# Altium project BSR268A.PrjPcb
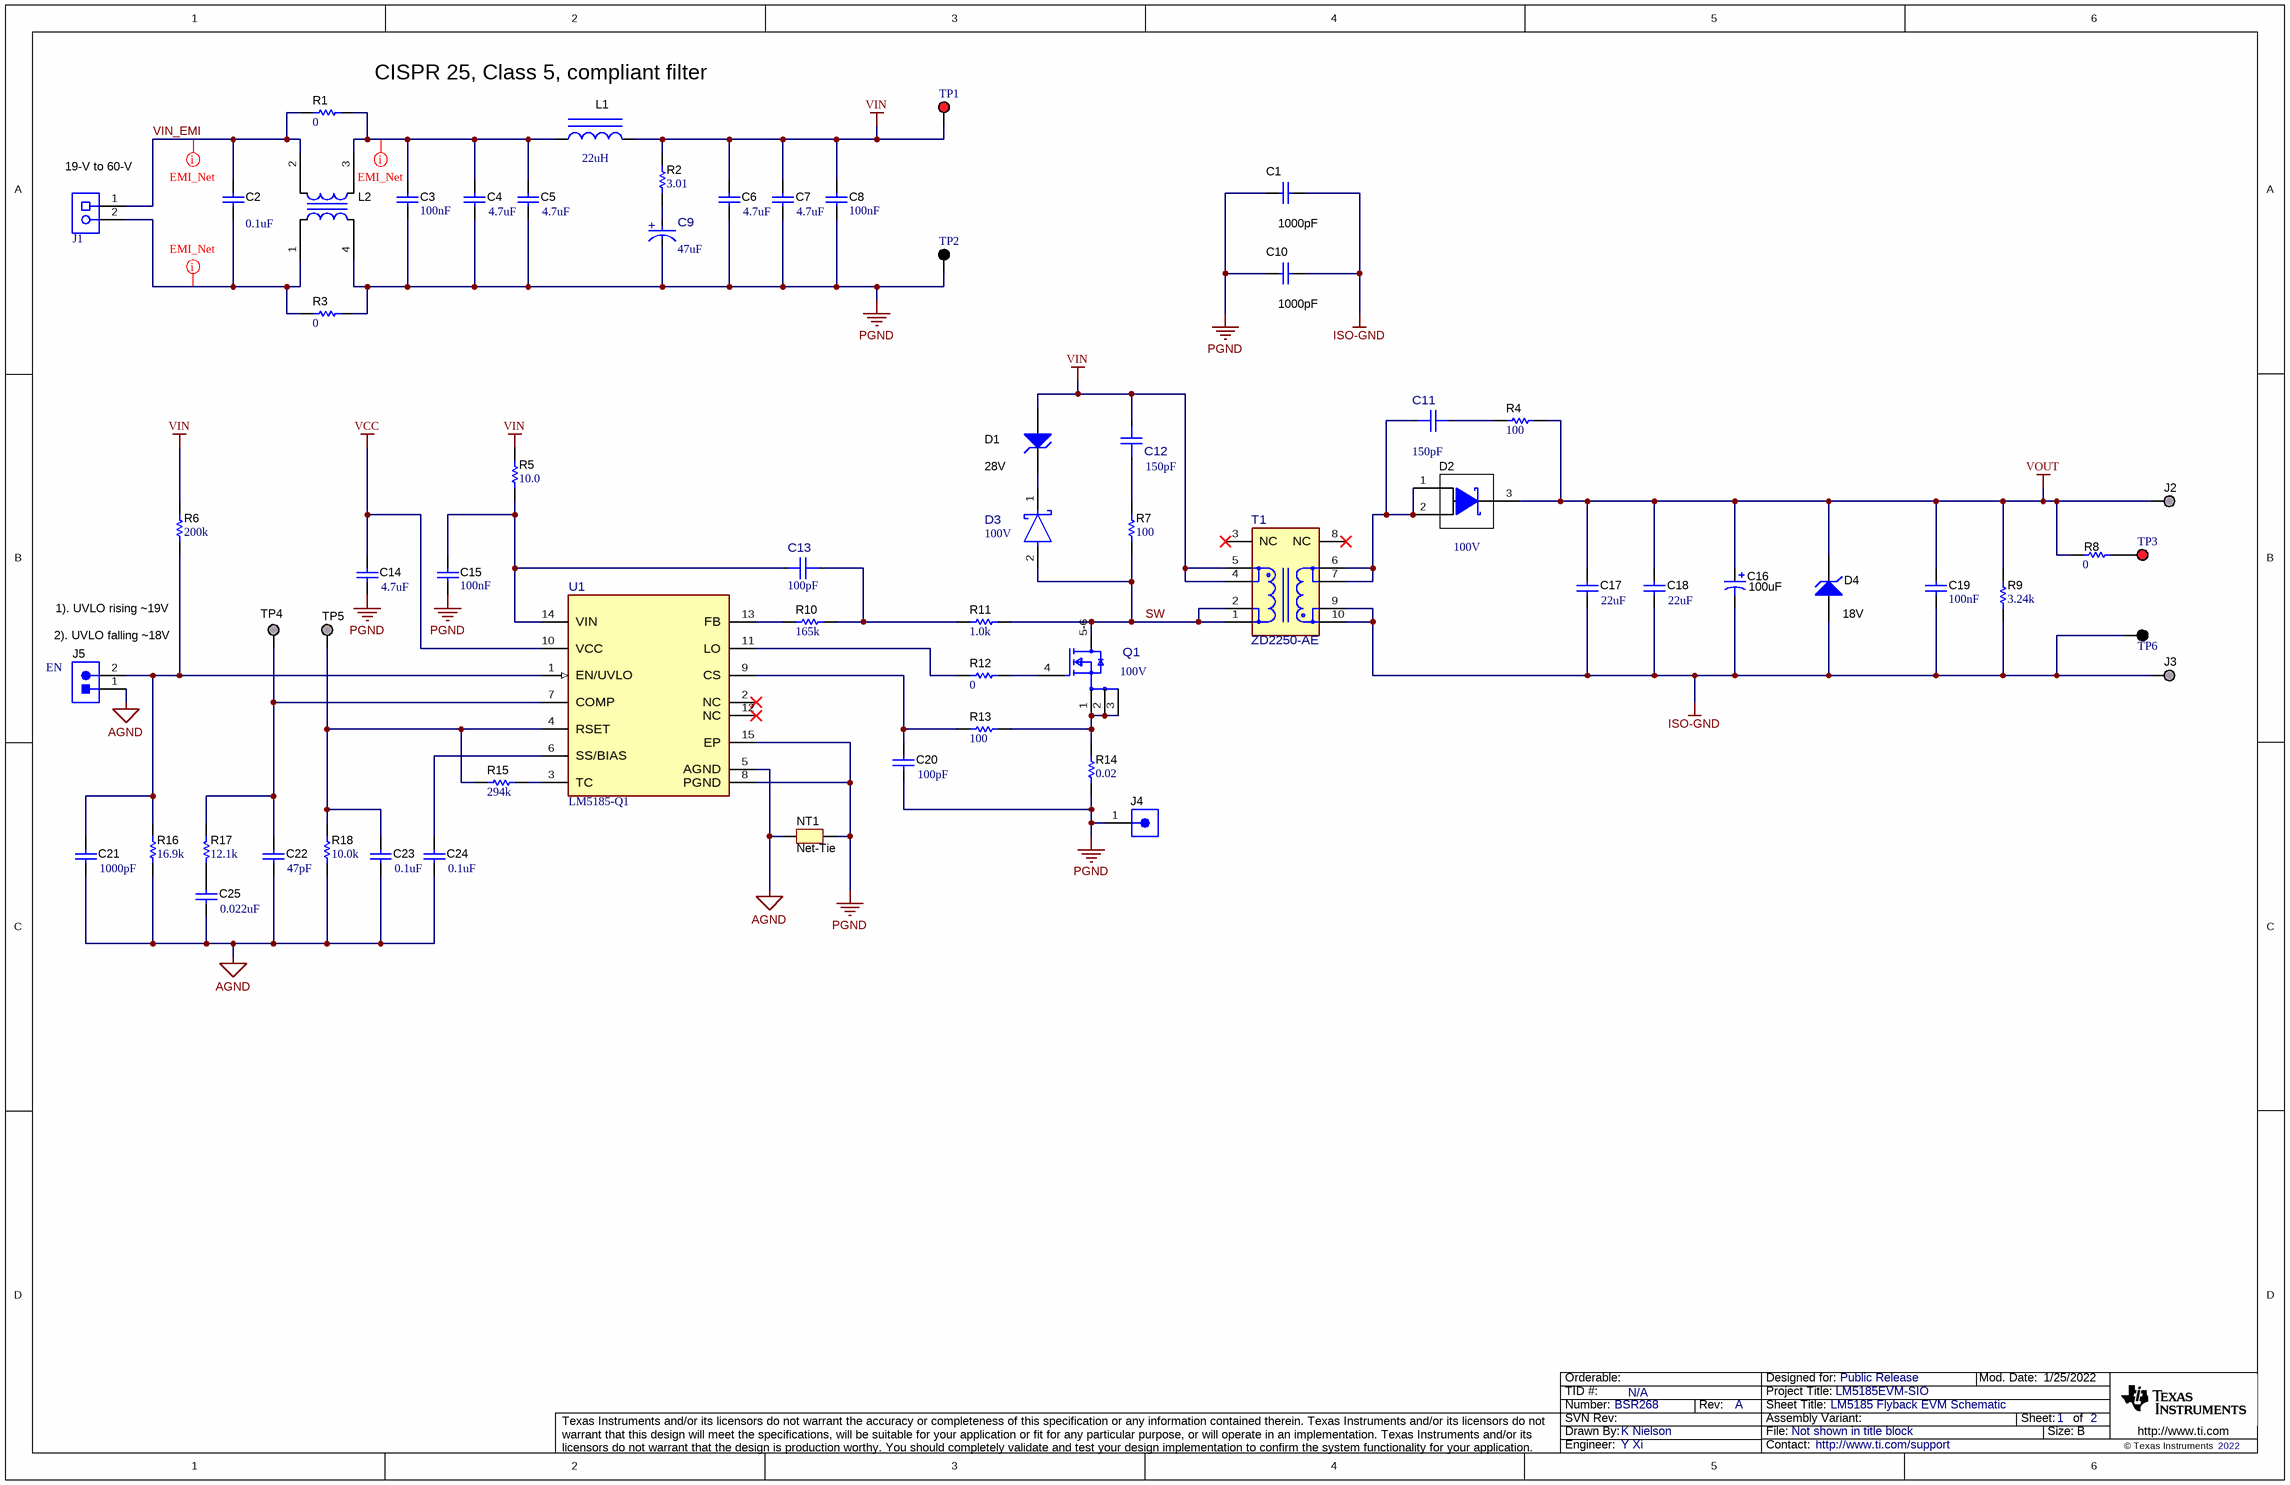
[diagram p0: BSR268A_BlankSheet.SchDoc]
CopyrightYear: 2022; PCB_Layout: K Nielson; PCB_Rev: A; PRJ_Customer: Public Release; PRJ_Engineer: Y Xi; PRJ_Number: BSR268; PRJ_Title: LM5185EVM-SIO; SCH_Rev: A; TechSupport: http://www.ti.com/support; TID: N/A
2 sheets, 91 parts. Net scope: global (net labels, ports and power ports of the same name join across sheets).
Board file: BSR268A.PcbDoc
Sheets:
  BSR268A_BlankSheet.SchDoc
  BSR268A_Hardware.SchDoc

## Sheet BSR268A_BlankSheet.SchDoc: LM5185 Flyback EVM Schematic
size 431 x 279 mm; Date: Not shown in title block; ApprovedBy: Not shown in title block; CheckedBy: Not shown in title block; Author: Not shown in title block; CompanyName: Not shown in title block; DrawnBy: K Nielson; Engineer: Not shown in title block; Organization: Not shown in title block; Address1: Not shown in title block; Address2: Not shown in title block; Address3: Not shown in title block; Address4: Not shown in title block; DocumentNumber: 2; Revision: Use project parameter SCH_Rev; SheetNumber: 1; SheetTotal: 2; PageSetup: Record=PageOptions¦CenterHorizontal=True¦CenterVertical=True¦PrintScale=1.00¦XCorrection=1.00¦YCorrection=1.00¦PrintKind=0¦BorderSize=5000000¦LeftOffset=0¦BottomOffset=0¦Orientation=2¦PaperLength=1000¦PaperWidth=1000¦Scale=100¦PaperSource=15¦PrintQuality=600¦MediaType=1¦DitherType=10¦PaperKind=Letter¦PrintScaleMode=1

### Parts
C1  ValueDisplayed: 1000pF  [1206_190]  (hidden comment: 202R18W102KV4E)
C2  ValueDisplayed: 0.1uF  [1206]  (hidden comment: GRM319R72A104KA01D)
C3  Cap_F: 100nF  [0603_HV]  (hidden comment: GRM188R72A104KA35D)
C4  ValueDisplayed: 4.7uF  [1210_220]  (hidden comment: C3225X7S2A475K200AB)
C5  ValueDisplayed: 4.7uF  [1210_220]  (hidden comment: C3225X7S2A475K200AB)
C6  ValueDisplayed: 4.7uF  [1210_220]  (hidden comment: C3225X7S2A475K200AB)
C7  ValueDisplayed: 4.7uF  [1210_220]  (hidden comment: C3225X7S2A475K200AB)
C8  Cap_F: 100nF  [0603]  (hidden comment: GRM188R72A104KA35D)
C9  ValueDisplayed: 47uF  [FP-865081757008_SMT_CAP_10MM3_10MM3-MFG]  (hidden comment: 865081757008)
C10  ValueDisplayed: 1000pF  [1206_190]  (hidden comment: 202R18W102KV4E)
C11  ValueDisplayed: 150pF  [FP-06031A151JAT2A_0603-MFG]  (hidden comment: 06031A151JAT2A)
C12  ValueDisplayed: 150pF  [FP-06031A151JAT2A_0603-MFG]  (hidden comment: 06031A151JAT2A)
C13  ValueDisplayed: 100pF  [FP-06031A101K4T2A_0603-IPC_C]  (hidden comment: 06031A101K4T2A)
C14  ValueDisplayed: 4.7uF  [0603L]  (hidden comment: GRM188Z71C475KE21D)
C15  Cap_F: 100nF  [0603L]  (hidden comment: GRM188R72A104KA35D)
C16  ValueDisplayed: 100uF  [SM_RADIAL_D8]  (hidden comment: EEE-FK1E101XP)
C17  ValueDisplayed: 22uF  [1210_270]  (hidden comment: GRM32ER71E226KE15L)
C18  ValueDisplayed: 22uF  [1210_270]  (hidden comment: GRM32ER71E226KE15L)
C19  Cap_F: 100nF  [0603]  (hidden comment: GRM188R72A104KA35D)
C20  ValueDisplayed: 100pF  [0603L]  (hidden comment: GRM1885C1H101JA01D)
C21  ValueDisplayed: 1000pF  [0603L]  (hidden comment: GCM1885C2A102JA16D)
C22  ValueDisplayed: 47pF  [0603L]  (hidden comment: CGA3E2NP01H470J080AA)
C23  ValueDisplayed: 0.1uF  [0603L]  (hidden comment: C0603C104J4RACTU)
C24  ValueDisplayed: 0.1uF  [0603L]  (hidden comment: C0603C104J4RACTU)
C25  ValueDisplayed: 0.022uF  [0603L]  (hidden comment: C0603C223K3RACTU)
D1  value 28V  [SMB]  (hidden comment: SMBJ5362B-TP)
D2  Vr_V: 100V  [POWERDI5]  (hidden comment: SDT5H100LP5-7)
D3  Vr_V: 100V  [FP-ACDBMT1100-HF_SOD-123H-MFG]  (hidden comment: ACDBMT1100-HF)
D4  value 18V  [SMA]  (hidden comment: SMAZ18-13-F)
J1  691 101 710 002  [Wurth_691101710002]  (value not drawn)
J2  1598-2  [Keystone1598-2]  (value not drawn)
J3  1598-2  [Keystone1598-2]  (value not drawn)
J4  1040  [CONN_1040]  (value not drawn)
J5  61300211121  [WURTH_61300211121]  (value not drawn)
L1  value 22uH  [XAL5050]  (hidden comment: XAL5050-223MEB)
L2  ACM70V-701-2PL-TL00  [IND_TDK_ACM7060]  (value not drawn)
NT1  Net-Tie  [Net-Tie_10milWide_30milLong]  (net tie, no BOM)
Q1  Drain To Source Breakdown Voltage: 100V  [FP-NVMFS021N10MCLT1G_DFN5-MFG]  (hidden comment: NVMFS021N10MCLT1G)
R1  ValueDisplayed: 0  [1206L]  (hidden comment: ERJ-8GEY0R00V)
R2  ValueDisplayed: 3.01  [0805_HV]  (hidden comment: RC0805FR-073R01L)
R3  ValueDisplayed: 0  [1206L]  (hidden comment: ERJ-8GEY0R00V)
R4  ValueDisplayed: 100  [1206]  (hidden comment: ERJ-8ENF1000V)
R5  ValueDisplayed: 10.0  [0603L]  (hidden comment: RC0603FR-0710RL)
R6  ValueDisplayed: 200k  [0603L]  (hidden comment: RC0603FR-07200KL)
R7  ValueDisplayed: 100  [1206]  (hidden comment: ERJ-8ENF1000V)
R8  ValueDisplayed: 0  [0805_HV]  (hidden comment: ERJ-6GEY0R00V)
R9  ValueDisplayed: 3.24k  [1206]  (hidden comment: ERJ-8ENF3241V)
R10  ValueDisplayed: 165k  [0603L]  (hidden comment: CRCW0603165KFKEA)
R11  ValueDisplayed: 1.0k  [0603L]  (hidden comment: RC0603JR-071KL)
R12  ValueDisplayed: 0  [0603L]  (hidden comment: RC0603JR-070RL)
R13  ValueDisplayed: 100  [0603L]  (hidden comment: RC0603FR-07100RL)
R14  ValueDisplayed: 0.02  [0612]  (hidden comment: PRL1632-R020-F-T1)
R15  ValueDisplayed: 294k  [0603L]  (hidden comment: RC0603FR-07294KL)
R16  ValueDisplayed: 16.9k  [0603L]  (hidden comment: RC0603FR-0716K9L)
R17  ValueDisplayed: 12.1k  [0603L]  (hidden comment: RC0603FR-0712K1L)
R18  ValueDisplayed: 10.0k  [0603L]  (hidden comment: RC0603FR-0710KL)
T1  ZD2250-AE  [FP-ZD2250-AE_SMT10_21MM97_16MM9-MFG]
TP1  5000  [Keystone5000]  (value not drawn)
TP2  5001  [Keystone5001]  (value not drawn)
TP3  5000  [Keystone5000]  (value not drawn)
TP4  TP_SM_1MM  [TP_SM_1MM]  (value not drawn)  (no BOM)
TP5  TP_SM_1MM  [TP_SM_1MM]  (value not drawn)  (no BOM)
TP6  5001  [Keystone5001]  (value not drawn)
U1  LM5185-Q1  [NEU0014AA-MFG]

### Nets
AGND: C21.2 C22.2 C23.1 C24.1 C25.2 J5.1 NT1.1 R16.1 R18.1 U1.5(AGND)
ISO-GND: C1.1 C10.1 C16.2(-) C17.1 C18.1 C19.2 D4.2(A) J3.1 R9.2 T1.9 T1.10 TP6.1
PGND: C1.2 C3.2 C4.2 C5.2 C6.2 C7.2 C8.2 C9.1(CATHODE) C10.2 C14.2 C15.2 C20.2 J4.1 L2.4 NT1.2 R3.2 R14.1 TP2.1 U1.8(PGND) U1.15(EP)
VCC: C14.1 U1.10(VCC)
VIN: C6.1 C7.1 C8.1 C12.2 D1.2(A) L1.2 R2.1 R5.2 R6.2 T1.4 T1.5 TP1.1
VOUT: C16.1(+) C17.2 C18.2 C19.1 D2.3(K) D4.1(K) J2.1 R4.2 R8.1 R9.1
SW: D3.2(Anode) Q1.5-6(D) R7.1 R11.2 T1.1 T1.2
VIN_EMI: C2.1 J1.1 L2.2 R1.1
NetC2_2: C2.2 J1.2 L2.1 R3.1
NetC3_1: C3.1 C4.1 C5.1 L1.1 L2.3 R1.2
NetC9_2: C9.2(ANODE) R2.2
NetC11_1: C11.1 D2.1(A) D2.2(A) T1.6 T1.7
NetC11_2: C11.2 R4.1
NetC12_1: C12.1 R7.2
NetC13_1: C13.1 R10.2 R11.1
NetC13_2: C13.2 C15.1 R5.1 U1.14(VIN)
NetC20_1: C20.1 R13.1 U1.9(CS)
NetC21_1: C21.1 J5.2 R6.1 R16.2 U1.1(EN/UVLO)
NetC22_1: C22.1 R17.2 TP4.1 U1.7(COMP)
NetC23_2: C23.2 R15.1 R18.2 TP5.1 U1.4(RSET)
NetC24_2: C24.2 U1.6(SS/BIAS)
NetC25_1: C25.1 R17.1
NetD1_1: D1.1(K) D3.1(Cathode)
NetQ1_1: Q1.1(S) Q1.2(S) Q1.3(S) R13.2 R14.2
NetQ1_4: Q1.4(G) R12.2
NetR8_2: R8.2 TP3.1
NetR10_1: R10.1 U1.13(FB)
NetR12_1: R12.1 U1.11(LO)
NetR15_2: R15.2 U1.3(TC)

Not connected (* = marked no-connect by the designer): T1 3(NC)* 8(NC)*; U1 2(NC)* 12(NC)*

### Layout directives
net class EMI_Net: NetC2_2, NetC3_1, VIN_EMI

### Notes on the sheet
- (near R1) CISPR 25, Class 5, compliant filter
- (near J1) 19-V to 60-V
- 1). UVLO rising
  9V
- (near J5) 2). UVLO falling
  8V
- (near J5) EN

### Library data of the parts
C1 C10 = CMP-0008572-2: CAP, CERM, 1000 pF, 2000 V, +/- 10%, X7R, 1206_190; Manufacturer: Johanson Technology; TaMin_C: -55°C; Polarized: N; SizeAreaWB_mm2: 10.92; Value1: Unknown; U/M: EA; Value: 1000pF; TaMax_C: 125°C; SizeZ_mm: 1.9; SizeX_mm: 3.2; SizeY_mm: 1.6; Cap_Case: 1206; Value2: 2000V; SizeArea_mm2: 5.12; Cap_F: 1nF; VDC_V: 2kV; AEC Category: Q200
C2 = CMP-0008881-2: CAP, CERM, 0.1 uF, 100 V, +/- 10%, X7R, 1206; Manufacturer: MuRata; TaMin_C: -55°C; Polarized: N; SizeAreaWB_mm2: 10.92; Value1: Unknown; U/M: EA; Value: 0.1uF; TaMax_C: 125°C; SizeZ_mm: 1.35; SizeX_mm: 3.2; SizeY_mm: 1.6; Value2: 100V; SizeArea_mm2: 5.12; Cap_F: 100nF; AEC Category: Q200
C3 C15 = CMP-0007469-4: CAP, CERM, 0.1 uF, 100 V, +/- 10%, X7R, 0603; Manufacturer: MuRata; TaMin_C: -55°C; Polarized: N; SizeAreaWB_mm2: 4.68; Value1: Unknown; U/M: EA; Value: 0.1uF; TaMax_C: 125°C; SizeZ_mm: 1; SizeX_mm: 1.6; SizeY_mm: 0.8; Cap_Case: 0603; Value2: 100V; SizeArea_mm2: 1.28; AEC Category: Q200
C4-C7 = CMP-0009134-2: CAP, CERM, 4.7 uF, 100 V, +/- 10%, X7S, 1210; Manufacturer: TDK; TaMin_C: -55°C; ESR_ohm: 4.236m; Polarized: N; SizeAreaWB_mm2: 14.7; Value1: 0.004236 ohm; U/M: EA; Value: 4.7uF; TaMax_C: 125°C; SizeZ_mm: 2.2; SizeX_mm: 3.2; SizeY_mm: 2.5; Value2: 100V; SizeArea_mm2: 8; Cap_F: 4.7µF; IRMS_A: 3.57337A; AEC Category: Q200
C8 C19 = CMP-0007469-4: CAP, CERM, 0.1 uF, 100 V, +/- 10%, X7R, 0603; Manufacturer: MuRata; TaMin_C: -55°C; Polarized: N; SizeAreaWB_mm2: 4.68; Value1: Unknown; U/M: EA; Value: 0.1uF; TaMax_C: 125°C; SizeZ_mm: 1; SizeX_mm: 1.6; SizeY_mm: 0.8; Value2: 100V; SizeArea_mm2: 1.28; AEC Category: Q200
C9 = CMP-0095714-1: Aluminum Electrolytic Capacitor 47uF 20% 80V 10.3x10.3x10.5mm SMT; Manufacturer: Wurth Electronics; IRMS_A: 160mA; SizeZ_mm: 10.5mm; Life: 2000Hours; AEC Qualified: No; Leakage Current: 37.6uA; Dissipation Factor: 10%; Value: 47µF
C11 = CMP-0096650-1: 0603 150 pF 100 V ±5 % Tolerance C0G/NP0 SMT Multilayer Ceramic Capacitor; Manufacturer: KYOCERA AVX; TempCo: 30ppm/°C; Value: 150pF; Tolerance_%: 5%; SizeZ_mm: 0.9mm; AEC Qualified: No; VDC_V: 100V; Temperature Characteristic: C0G
C12 = CMP-0096650-1: 0603 150 pF 100 V ±5 % Tolerance C0G/NP0 SMT Multilayer Ceramic Capacitor; Manufacturer: KYOCERA AVX; TempCo: 30ppm/°C; Tolerance_%: 5%; SizeZ_mm: 0.9mm; AEC Qualified: No; VDC_V: 100V; Temperature Characteristic: C0G; Value: 150pF
C13 = CMP-0089170-1: 100pF ±10% 100V Ceramic Capacitor C0G, NP0 0603 (1608 Metric); Manufacturer: AVX; TempCo: 30ppm/°C; SizeZ_mm: 0.9mm; AEC Qualified: Yes; AEC Grade: Grade 1
C14 = CMP-0064936-4: CAP, CERM, 4.7 uF, 16 V,+/- 10%, X7R, 0603; Manufacturer: MuRata; TaMin_C: -55°C; Polarized: N; SizeAreaWB_mm2: 4.68; Value1: Unknown; U/M: EA; Value: 4.7uF; TaMax_C: 125°C; SizeZ_mm: 1; SizeX_mm: 1.6; SizeY_mm: 0.8; Cap_Case: 0603; Value2: 16V; SizeArea_mm2: 1.28; Cap_F: 4.7µF; AEC Category: Q200
C16 = CMP-0010711-1: CAP, AL, 100 uF, 25 V, +/- 20%, 0.34 ohm, AEC-Q200 Grade 2, SMD; Manufacturer: Panasonic; TaMin_C: -55°C; ESR_ohm: 3.4d; Polarized: Y; SizeAreaWB_mm2: 84.28; U/M: EA; Value: 100uF; TaMax_C: 105°C; SizeZ_mm: 7.7; SizeX_mm: 7.8; SizeY_mm: 6.6; Cap_Case: D8; Value2: 25V; SizeArea_mm2: 51.48; CompType: Capacitor; Cap_F: 100µF; IRMS_A: 2.8dA; AEC Grade: 2; AEC Category: Q200
C17 C18 = CMP-0009224-2: CAP, CERM, 22 uF, 25 V, +/- 10%, X7R, 1210; Manufacturer: MuRata; TaMin_C: -55°C; Polarized: N; SizeAreaWB_mm2: 14.7; Value1: Unknown; U/M: EA; Value: 22uF; TaMax_C: 125°C; SizeZ_mm: 2.7; SizeX_mm: 3.2; SizeY_mm: 2.5; Cap_Case: 1210; Value2: 25V; SizeArea_mm2: 8; Cap_F: 22µF; AEC Category: Q200
C20 = CMP-0007171-4: CAP, CERM, 100 pF, 50 V, +/- 5%, C0G/NP0, 0603; Manufacturer: MuRata; TaMin_C: -55°C; Polarized: N; SizeAreaWB_mm2: 4.68; Value1: Unknown; U/M: EA; Value: 100pF; TaMax_C: 125°C; SizeZ_mm: 1; SizeX_mm: 1.6; SizeY_mm: 0.8; Cap_Case: 0603; Value2: 50V; SizeArea_mm2: 1.28; AEC Category: Q200
C21 = CMP-0007131-4: CAP, CERM, 1000 pF, 100 V, +/- 5%, C0G/NP0, AEC-Q200 Grade 1, 0603; Manufacturer: MuRata; TaMin_C: -55°C; Polarized: N; SizeAreaWB_mm2: 4.68; Value1: Unknown; U/M: EA; Value: 1000pF; TaMax_C: 125°C; SizeZ_mm: 1; SizeX_mm: 1.6; SizeY_mm: 0.8; Cap_Case: 0603; Value2: 100V; SizeArea_mm2: 1.28; AEC Qualified: Y; Cap_F: 1nF; AEC Category: Q200
C22 = CMP-0080062-1: CAP, CERM, 47 pF, 50 V,+/- 5%, C0G/NP0, AEC-Q200 Grade 0, 0603; Manufacturer: TDK; TaMin_C: -55°C; Polarized: N; SizeAreaWB_mm2: 4.68; U/M: EA; Value: 47pF; TaMax_C: 150°C; SizeZ_mm: 1; SizeX_mm: 1.6; SizeY_mm: 0.8; Cap_Case: 0603; Value2: 50V; SizeArea_mm2: 1.28; AEC Qualified: Y; AEC Grade: 0; AEC Category: Q200
C23 C24 = CMP-0006857-4: CAP, CERM, 0.1 uF, 16 V, +/- 5%, X7R, 0603; Manufacturer: Kemet; TaMin_C: -55°C; Polarized: N; SizeAreaWB_mm2: 4.68; Value1: Unknown; U/M: EA; Value: 0.1uF; TaMax_C: 125°C; SizeZ_mm: 1; SizeX_mm: 1.6; SizeY_mm: 0.8; Cap_Case: 0603; Value2: 16V; SizeArea_mm2: 1.28; Cap_F: 100nF; AEC Category: Q200
C25 = CMP-0006899-4: CAP, CERM, 0.022 uF, 25 V, +/- 10%, X7R, 0603; Manufacturer: Kemet; TaMin_C: -55°C; Polarized: N; SizeAreaWB_mm2: 4.68; Value1: Unknown; U/M: EA; TaMax_C: 125°C; SizeZ_mm: 1; SizeX_mm: 1.6; SizeY_mm: 0.8; Cap_Case: 0603; Value2: 25V; SizeArea_mm2: 1.28; Cap_F: 22nF; AEC Category: Q200
D1 = CMP-0005655-4: Diode, Zener, 28 V, 5 W, SMB; Manufacturer: Micro Commercial Components; Power_W: 5W; SizeAreaWB_mm2: 44.156; RJA_CperW: 226; SizeX_mm: 5.6; SizeArea_mm2: 21.336; SizeY_mm: 3.81; SizeZ_mm: 2.6; AEC Category: Q101
D2 = CMP-0077681-2: Diode, Schottky, 100 V, 5 A, PowerDI5; Manufacturer: Diodes Inc.; SizeAreaWB_mm2: 49.56; Value1: 5A; TJmax_C: 150°C; SizeZ_mm: 1.05; SizeY_mm: 3.9; AEC Qualified: N; Value: 100V; Value2: 0.66V; SizeX_mm: 6.4; SizeArea_mm2: 24.96; Vf_V: 660mV; AEC Category: Q101
D3 = CMP-0098302-1: Diode 100 V 1A Surface Mount SOD-123H; Manufacturer: Comchip Technology; TJmax_C: 150°C; SizeZ_mm: 1mm; AEC Qualified: Yes; AEC Grade: Grade 0; Cap_F: 120pF; Max Surge Forward Current: 30A; Peak Reverse Current: 0.5mA
D4 = CMP-0005526-4: Diode, Zener, 18 V, 1 W, AEC-Q101, SMA; Manufacturer: Diodes Inc.; SizeAreaWB_mm2: 37.3428; AEC Category: Q101; Power_W: 1W; SizeY_mm: 2.92; SizeZ_mm: 2.87; SizeX_mm: 5.59; SizeArea_mm2: 16.3228; AEC Qualified: Y; RJA_CperW: 125
J1 = CMP-0054828-1: Terminal Block, 5 mm, 2x1, Tin, TH; Manufacturer: Wurth Elektronik; CNHeader: FALSE; Green_Lifecycle: Active; Green_REACh: Passed; CT: TRUE
J2 J3 = CMP-0055121-1: Terminal, Turret, TH, Triple; Manufacturer: Keystone; CT: FALSE; Green_REACh: Passed; CompType: Turret Terminal; Green_Lifecycle: Active
J4 = CMP-0055161-1: Manufacturer: Keystone; CNHeader: FALSE; Green_Lifecycle: Active; Green_REACh: Passed; CompType: Test Point; CT: TRUE
J5 = CMP-0054794-2: Header, 2.54 mm, 2x1, Gold, TH; Manufacturer: Wurth Elektronik; Shrouded: N; Gender: Male; Green_REACh: Passed; Pitch_mm: 2.54; Green_Lifecycle: Active; Row_Count: 1; Cert_UL: Y
L1 = CMP-0061651-2: Inductor, Shielded, Composite, 22 uH, 3.4 A, 0.1 ohm, SMD; Manufacturer: Coilcraft; Isat: 3.6A @ 30% inductance drop; Ind_H: 22µH; DCR_ohm: 0.1; SizeZ_mm: 5.1; Irms: 3.4A @ 40C rise; Green_Lifecycle: Not Set; SizeAreaWB_mm2: 54.4544; Green_REACh: Incomplete; Value1: 0.1 ohm; Imax_A: 3.4A; SizeX_mm: 5.28; SizeY_mm: 5.48; SizeArea_mm2: 28.9344; AEC Category: Q200
L2 = CMP-0085405-1: Coupled inductor, 0.015 ohm, AEC-Q200 Grade 1, SMD; Manufacturer: TDK; DCR_ohm: 0.015; AEC Qualified: Y; AEC Category: Q200; AEC Grade: 1
NT1 = CMP-0078142-6: Single point connection between nets.
Q1 = CMP-0032635-1: N-Channel 100 V 8.4A (Ta), 31A (Tc) 3.6W (Ta), 49W (Tc) Surface Mount 5-DFN (5x6) (8-SOFL); Manufacturer: onsemi; AEC Qualified: Yes; QgTyp_nC: 13nC @ 10V; Rdson45_ohm: 19m; SizeZ_mm: 1.1mm; VdsMax_V: 1.3V; Vgs_V: 20V; ChMode: False; AEC Grade: Grade 0; Input Capacitace At Vds: 850pF @ 50V; Number Of Channels: 1; Pulse Drain Current: 159A; Reverse Recovery Charge: 18nC; Reverse Recovery Time: 29ns; Rthja Max: 42°C/W; Standoff Height: 0mm; Threshold Vgs Max: 3V; Threshold Vgs Min: 1V; TJmax_C: +175°C; Transconductance: 24S; Turn Off Delay Time: 19ns; Turn On Delay Time: 6.4ns; Typ Forward Diode Voltage: 0.83V
R1 R3 = CMP-0018748-3: RES, 0, 5%, 0.25 W, AEC-Q200 Grade 0, 1206; Manufacturer: Panasonic; Power_W: 250mW; TempCo: 600 ppm/C; Value_Code: 0000; Value: 0; EIA_Code: E24; SizeX_mm: 3.2; SizeY_mm: 1.6; SizeZ_mm: 1.35; Value2: 0.25W; SizeArea_mm2: 5.12; AEC Qualified: Y; VDC_V: 200V; AEC Category: Q200; SizeAreaWB_mm2: 10.92
R2 = CMP-0021914-2: RES, 3.01, 1%, 0.125 W, 0805; Manufacturer: Yageo America; Power_W: 125mW; TempCo: 200 ppm/C; Value_Code: 3R01; Value: 3.01; EIA_Code: E96; SizeX_mm: 2; SizeY_mm: 1.25; SizeZ_mm: 1.45; Value2: 0.125W; SizeArea_mm2: 2.5; VDC_V: 150V; AEC Category: Q200; U/M: EA
R4 R7 = CMP-0017282-3: RES, 100, 1%, 0.25 W, AEC-Q200 Grade 0, 1206; Manufacturer: Panasonic; Power_W: 250mW; TempCo: 100 ppm/C; Value_Code: 100R; Value: 100; EIA_Code: E96; SizeX_mm: 3.2; SizeY_mm: 1.6; SizeZ_mm: 1.35; Value2: 0.25W; SizeArea_mm2: 5.12; AEC Qualified: Y; VDC_V: 200V; AEC Category: Q200; AEC Grade: 0; SizeAreaWB_mm2: 10.92
R5 = CMP-0022751-4: RES, 10.0, 1%, 0.1 W, 0603; Manufacturer: Yageo; Power_W: 100mW; TempCo: 100 ppm/C; Value_Code: 10R0; Value: 10.0; EIA_Code: E96; Res_ohm: 10; SizeX_mm: 1.6; SizeY_mm: 0.8; SizeZ_mm: 1; Value2: 0.1W; SizeArea_mm2: 1.28; AEC Qualified: N; VDC_V: 75V; AEC Category: Q200; SizeAreaWB_mm2: 4.68
R6 = CMP-0022901-4: RES, 200 k, 1%, 0.1 W, 0603; Manufacturer: Yageo; Power_W: 100mW; TempCo: 100 ppm/C; Value: 200k; EIA_Code: E96; SizeX_mm: 1.6; SizeY_mm: 0.8; SizeZ_mm: 1; Value2: 0.1W; SizeArea_mm2: 1.28; AEC Qualified: N; VDC_V: 75V; AEC Category: Q200; SizeAreaWB_mm2: 4.68
R8 = CMP-0020616-3: RES, 0, 5%, 0.125 W, AEC-Q200 Grade 0, 0805; Manufacturer: Panasonic; Power_W: 125mW; TempCo: 600 ppm/C; Value_Code: 0000; Value: 0; EIA_Code: E24; SizeX_mm: 2; SizeY_mm: 1.25; SizeZ_mm: 1.45; Value2: 0.125W; SizeArea_mm2: 2.5; AEC Qualified: Y; VDC_V: 150V; AEC Category: Q200; SizeAreaWB_mm2: 6.75
R9 = CMP-0017537-3: RES, 3.24 k, 1%, 0.25 W, AEC-Q200 Grade 0, 1206; Manufacturer: Panasonic; Power_W: 250mW; TempCo: 100 ppm/C; Value_Code: 3k24; Value: 3.24k; EIA_Code: E96; SizeX_mm: 3.2; SizeY_mm: 1.6; SizeZ_mm: 1.35; Value2: 0.25W; SizeArea_mm2: 5.12; AEC Qualified: Y; VDC_V: 200V; AEC Category: Q200; AEC Grade: 0; SizeAreaWB_mm2: 10.92
R10 = CMP-0022075-4: RES, 165 k, 1%, 0.1 W, AEC-Q200 Grade 0, 0603; Manufacturer: Vishay-Dale; Power_W: 100mW; TempCo: 100 ppm/C; Value: 165k; EIA_Code: E96; SizeX_mm: 1.6; SizeY_mm: 0.8; SizeZ_mm: 1; Value2: 0.1W; SizeArea_mm2: 1.28; AEC Qualified: Y; VDC_V: 75V; AEC Category: Q200; AEC Grade: 0
R11 = CMP-0025899-5: RES, 1.0 k, 5%, 0.1 W, 0603; Manufacturer: Yageo; Power_W: 100mW; TempCo: 100 ppm/C; Value_Code: 1k00; Value: 1.0k; EIA_Code: E24; Res_ohm: 1k; SizeX_mm: 1.6; SizeZ_mm: 1; Value2: 0.1W; SizeArea_mm2: 1.28; AEC Qualified: N; VDC_V: 75V; AEC Category: Q200; SizeY_mm: 0.8; SizeAreaWB_mm2: 4.68
R12 = CMP-0025885-5: RES, 0, 5%, 0.1 W, 0603; Manufacturer: Yageo; Power_W: 100mW; TempCo: 200 ppm/C; Value_Code: 0000; Value: 0; EIA_Code: E24; SizeX_mm: 1.6; SizeY_mm: 0.8; SizeZ_mm: 1; Value2: 0.1W; SizeArea_mm2: 1.28; AEC Qualified: N; AEC Category: Q200; VDC_V: 75V; SizeAreaWB_mm2: 4.68
R13 = CMP-0022736-4: RES, 100, 1%, 0.1 W, 0603; Manufacturer: Yageo; Power_W: 100mW; TempCo: 100 ppm/C; Value_Code: 100R; Value: 100; EIA_Code: E96; SizeX_mm: 1.6; SizeY_mm: 0.8; SizeZ_mm: 1; Value2: 0.1W; SizeArea_mm2: 1.28; AEC Qualified: N; VDC_V: 75V; AEC Category: Q200; SizeAreaWB_mm2: 4.68
R14 = CMP-0015215-3: RES, 0.02, 1%, 1 W, 0612; Manufacturer: Susumu Co Ltd; Power_W: 1W; TempCo: 100 ppm/C; SizeAreaWB_mm2: 10.92; Value_Code: R020; U/M: EA; Value: 0.02; EIA_Code: E96; Res_ohm: 20m; SizeX_mm: 1.6; SizeY_mm: 3.2; SizeZ_mm: 0.85; SizeArea_mm2: 5.12; AEC Category: Q200
R15 = CMP-0022977-4: RES, 294 k, 1%, 0.1 W, 0603; Manufacturer: Yageo; Power_W: 100mW; TempCo: 100 ppm/C; Value: 294k; EIA_Code: E96; SizeX_mm: 1.6; SizeY_mm: 0.8; SizeZ_mm: 1; Value2: 0.1W; SizeArea_mm2: 1.28; AEC Qualified: N; VDC_V: 75V; AEC Category: Q200; SizeAreaWB_mm2: 4.68
R16 = CMP-0022830-5: RES, 16.9 k, 1%, 0.1 W, 0603; Manufacturer: Yageo; Power_W: 100mW; TempCo: 100 ppm/C; Value_Code: 16k9; Value: 16.9k; EIA_Code: E96; SizeX_mm: 1.6; SizeY_mm: 0.8; SizeZ_mm: 1; Value2: 0.1W; SizeArea_mm2: 1.28; AEC Qualified: N; VDC_V: 75V; AEC Category: Q200; SizeAreaWB_mm2: 4.68
R17 = CMP-0022776-5: RES, 12.1 k, 1%, 0.1 W, 0603; Manufacturer: Yageo; Power_W: 100mW; TempCo: 100 ppm/C; Value_Code: 12k1; Value: 12.1k; EIA_Code: E96; SizeX_mm: 1.6; SizeY_mm: 0.8; SizeZ_mm: 1; Value2: 0.1W; SizeArea_mm2: 1.28; AEC Qualified: N; VDC_V: 75V; AEC Category: Q200; SizeAreaWB_mm2: 4.68
R18 = CMP-0022746-5: RES, 10.0 k, 1%, 0.1 W, 0603; Manufacturer: Yageo; Power_W: 100mW; TempCo: 100 ppm/C; Value_Code: 10k0; Value: 10.0k; EIA_Code: E96; Res_ohm: 10k; SizeX_mm: 1.6; SizeY_mm: 0.8; SizeZ_mm: 1; Value2: 0.1W; SizeArea_mm2: 1.28; AEC Qualified: N; VDC_V: 75V; AEC Category: Q200; SizeAreaWB_mm2: 4.68
T1 = CMP-0097601-1: EFD15 10PIN SMD FLYBACK TRANSFORMER; Manufacturer: Coilcraft; SizeZ_mm: 8.8mm; AEC Qualified: No; Ns1toNp: 1:1; Voltage_Isolation_Vrms: 2000Vrms; Ind_H: 12µH
TP1 TP3 = CMP-0055137-2: Test Point, Miniature, Red, TH; Manufacturer: Keystone Electronics; Green_REACh: Passed; CT: TRUE; ContactFinish: Silver; CNHeader: FALSE; Green_Lifecycle: Active
TP2 TP6 = CMP-0055138-2: Test Point, Miniature, Black, TH; Manufacturer: Keystone Electronics; ContactFinish: Silver; CNHeader: FALSE; Green_Lifecycle: Active; Green_REACh: Passed; CT: TRUE
TP4 TP5 = CMP-0003825-1: 1mm Test Point, SMT; Manufacturer: Any
U1 = CMP-0091530-1: 120-VIN PSR Flyback Automotive DC/DC Controller With Low IQ and Low EMI, HTSSOP14; Manufacturer: Texas Instruments; AEC Qualified: Yes; Number Of Outputs: 1; TaMax_C: +125°C; Standoff Height: 0.05mm; AEC Grade: Grade 1; Max Supply Voltage: 120V; SizeZ_mm: 1.1mm; TJmax_C: +150°C; TaMin_C: -40°C; Min Supply Voltage: 4.5V

## Sheet BSR268A_Hardware.SchDoc: LM5185 Flyback EVM Hardware
size 431 x 279 mm; Date: Not shown in title block; ApprovedBy: Not shown in title block; CheckedBy: Not shown in title block; Author: Not shown in title block; CompanyName: Not shown in title block; DrawnBy: K Nielson; Engineer: Not shown in title block; Organization: Not shown in title block; Address1: Not shown in title block; Address2: Not shown in title block; Address3: Not shown in title block; Address4: Not shown in title block; DocumentNumber: 3; Revision: Use project parameter SCH_Rev; SheetNumber: 2; SheetTotal: 2; PageSetup: Record=PageOptions¦CenterHorizontal=True¦CenterVertical=True¦PrintScale=1.00¦XCorrection=1.00¦YCorrection=1.00¦PrintKind=0¦BorderSize=5000000¦LeftOffset=0¦BottomOffset=0¦Orientation=2¦PaperLength=1000¦PaperWidth=1000¦Scale=100¦PaperSource=15¦PrintQuality=600¦MediaType=1¦DitherType=10¦PaperKind=Letter¦PrintScaleMode=1
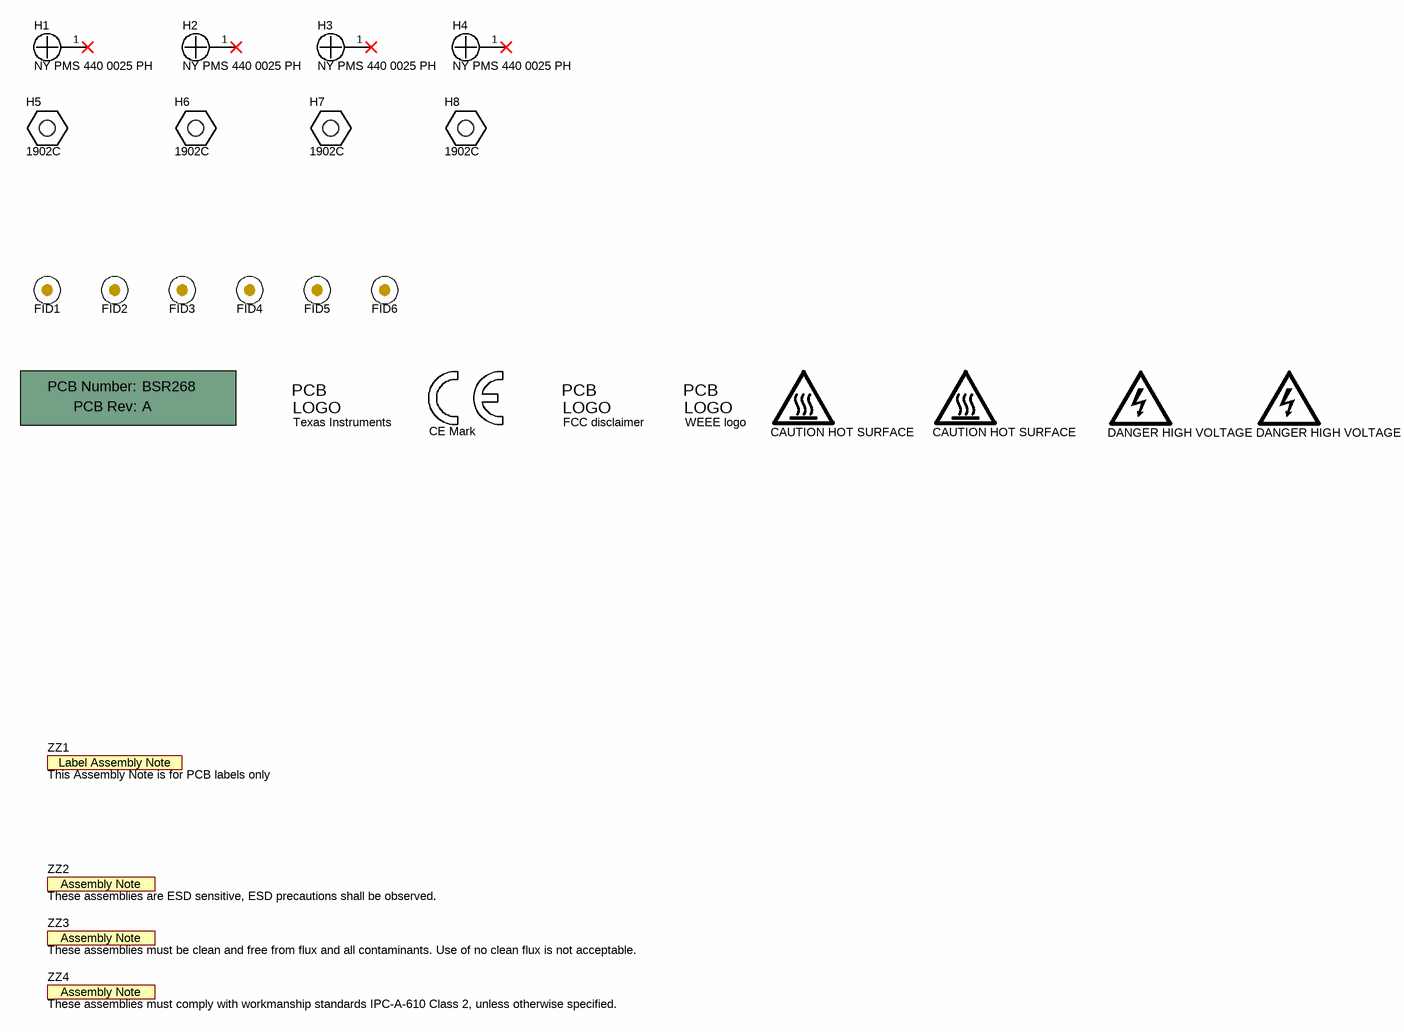
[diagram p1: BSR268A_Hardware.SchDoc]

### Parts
!PCB1  Printed Circuit Board  (value not drawn)  (mechanical)
FID1  Fiducial  [Fiducial10-20]  (value not drawn)
FID2  Fiducial  [Fiducial10-20]  (value not drawn)
FID3  Fiducial  [Fiducial10-20]  (value not drawn)
FID4  Fiducial  [Fiducial10-20]  (value not drawn)
FID5  Fiducial  [Fiducial10-20]  (value not drawn)
FID6  Fiducial  [Fiducial10-20]  (value not drawn)
H1  NY PMS 440 0025 PH  [NY PMS 440 0025 PH]
H2  NY PMS 440 0025 PH  [NY PMS 440 0025 PH]
H3  NY PMS 440 0025 PH  [NY PMS 440 0025 PH]
H4  NY PMS 440 0025 PH  [NY PMS 440 0025 PH]
H5  1902C  [Keystone_1902C]
H6  1902C  [Keystone_1902C]
H7  1902C  [Keystone_1902C]
H8  1902C  [Keystone_1902C]
Logo1  CE Mark  [CE_Mark_5mm]  (no BOM)
Logo2  Texas Instruments  [TI_Stacked_Overlay_Small]  (no BOM)
Logo3  FCC disclaimer  [FCC_disclaimer]  (no BOM)
Logo4  WEEE logo  [WEEE_Minimum]  (no BOM)
Logo5  CAUTION HOT SURFACE  [IEC_HotSurface_Small]  (no BOM)
Logo6  CAUTION HOT SURFACE  [IEC_HotSurface_Small]  (no BOM)
Logo7  DANGER HIGH VOLTAGE  [IEC_HighVoltage_Small]  (no BOM)
Logo8  DANGER HIGH VOLTAGE  [IEC_HighVoltage_Small]  (no BOM)
ZZ1  This Assembly Note is for PCB labels only  [AssemblyNoteLabel]  (no BOM)
ZZ2  These assemblies are ESD sensitive, ESD precautions shall be observed.  [AssemblyNote]  (no BOM)
ZZ3  These assemblies must be clean and free from flux and all contaminants. Use of no clean flux is not acceptable.  [AssemblyNote]  (no BOM)
ZZ4  These assemblies must comply with workmanship standards IPC-A-610 Class 2, unless otherwise specified.  [AssemblyNote]  (no BOM)

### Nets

Not connected (* = marked no-connect by the designer): H1 1*; H2 1*; H3 1*; H4 1*

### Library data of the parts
!PCB1 = CMP-0003618-2: Manufacturer: Any; PartNumber: BSR268
FID1-FID6 = CMP-0077181-1: Fiducial mark.  There is nothing to buy or mount.
H1-H4 = CMP-0003617-1: Machine Screw, Round, #4-40 x 1/4, Nylon, Philips panhead; Manufacturer: B&F Fastener Supply; CompType: Hardware
H5-H8 = CMP-0003610-1: Standoff, Hex, 0.5"L #4-40 Nylon; Manufacturer: Keystone; CompType: Hardware
Logo1 = CMP-0074844-1: SymbolCreator: a0412235
Logo2 = CMP-0074838-1: Texas Instrument Corporate Signature; SymbolCreator: a0412235; Lib Reference: TI_Logo; Library Reference: Logo
Logo3 = CMP-0074847-1: FCC_disclaimer; Library Reference: Logo
Logo4 = CMP-0074769-3: Manufacturer: Texas Instruments; AEC Category: Q200; CompType: IC
Logo5 Logo6 = CMP-0074837-2: IEC 61010-1 Hot Surface Warning; Manufacturer: Texas Instruments; SymbolCreator: a0412235; AEC Category: Q200; CompType: IC
Logo7 Logo8 = CMP-0074835-1: IEC 61010-1 High Voltage Warning; SymbolCreator: a0412235
ZZ1 = CMP-0003616-3
ZZ2 = CMP-0077236-1
ZZ3 = CMP-0077237-1
ZZ4 = CMP-0077238-1

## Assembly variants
001: not fitted C10 C13 C23 L2 R15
